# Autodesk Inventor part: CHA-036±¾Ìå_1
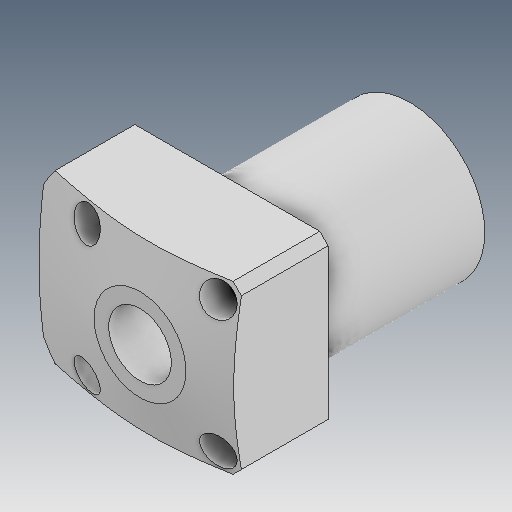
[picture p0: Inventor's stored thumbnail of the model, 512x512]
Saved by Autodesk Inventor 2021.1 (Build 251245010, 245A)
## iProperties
Created: 2019-12
Part Number: CHA-036±¾Ìå_1
Material: Ogólny
Document SubType Name: Modeling
Designer: user
Density: 1 g/cm^3
Appearance: Domyślna
Author: user
Revision Number: ÈÎºÎ
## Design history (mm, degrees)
feature "NONE"
node "Bryła1"
